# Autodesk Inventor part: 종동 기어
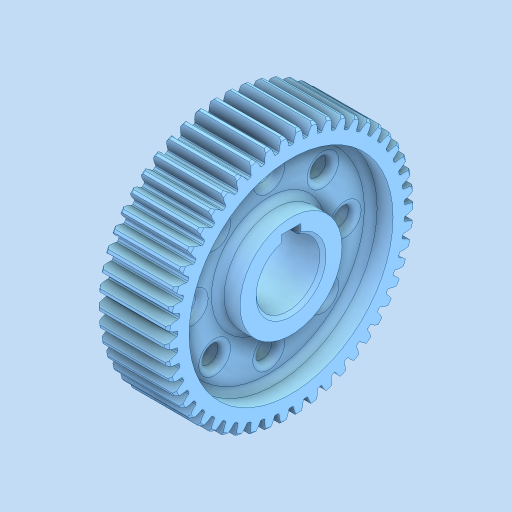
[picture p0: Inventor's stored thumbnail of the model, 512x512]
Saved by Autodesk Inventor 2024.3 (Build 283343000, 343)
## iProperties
Created: 2025-11
Part Number: 종동 기어
Material: 강철, 탄소
Document SubType Name: Modeling
Designer: PC2-02
Density: 7.85 g/cm^3
Appearance: 기본값
Author: jhkim
Sending System: Autodesk Inventor 2026
Preprocessor: ST-DEVELOPER v20.1
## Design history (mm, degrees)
node "종동 기어1"
node "솔리드2"
node "솔리드1"
